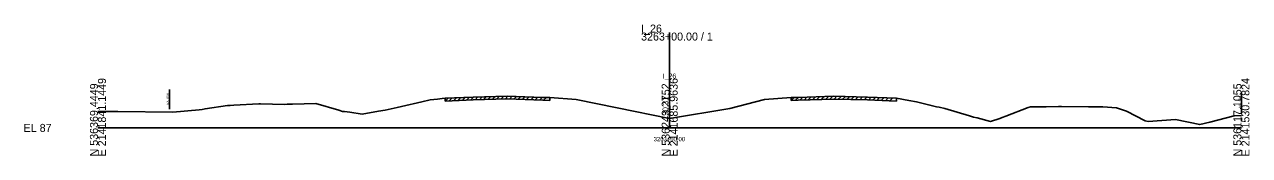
# Model space of a CAD drawing. Extents: x -13101 to 4803, y -924 to 22390.
# Drawn here: x 2974.3 to 3402.8, y 11490.3 to 11536.3 of the extents above; entities that cross this region are included whole.
import ezdxf

# ---------------------------------------------------------------- set-up
doc = ezdxf.new("R2010")
doc.units = 0
for name, color, linetype in [('RD_GPK_XS_Cell', 7, 'Continuous'), ('RD_XS_ExGround', 7, 'Continuous'), ('RD_XS_ExPaveRet', 7, 'Continuous'), ('RD_XS_ExRW', 7, 'Continuous'), ('RD_XS_TX_Baseline', 7, 'Continuous'), ('RD_XS_TX_Elev_EX', 7, 'Continuous'), ('RD_XS_TX_Station', 7, 'Continuous')]:
    doc.layers.add(name, color=color, linetype=linetype)

msp = doc.modelspace()

# ---------------------------------------------------------------- linework, layer by layer
at = {"layer": 'RD_GPK_XS_Cell'}
for p, q in [((3200, 11500), (3200, 11533.42)), ((3000, 11500), (3200, 11500)), ((3200, 11500), (3400, 11500))]:
    msp.add_line(p, q, dxfattribs=at)
at = {"layer": 'RD_XS_ExGround'}
msp.add_lwpolyline([(3000, 11505.78), (3006.19, 11505.77), (3006.99, 11505.77), (3026.2, 11505.49), (3035.4, 11506.29), (3036.49, 11506.46), (3037.47, 11506.71), (3045.37, 11507.86), (3046.21, 11507.88), (3047.56, 11507.96), (3056.3, 11508.42), (3056.84, 11508.45), (3065.24, 11508.24), (3066.22, 11508.32), (3068.08, 11508.36), (3076.22, 11508.59), (3084.29, 11506.27), (3085.52, 11505.73), (3086.23, 11505.72), (3088.07, 11505.49), (3092.44, 11504.87), (3098.2, 11505.9), (3100.45, 11506.25), (3104.65, 11507.19), (3106.23, 11507.56), (3113.29, 11509.19), (3116.24, 11509.88), (3118.82, 11510.11), (3120.43, 11510.26), (3121.42, 11510.37), (3131.22, 11510.83), (3143.14, 11511.14), (3155.6, 11510.7), (3158.11, 11510.64), (3167.24, 11510), (3181.62, 11507.05), (3200, 11503.31), (3221, 11506.84), (3233.12, 11509.99), (3242.5, 11510.61), (3244.9, 11510.71), (3257.44, 11511.1), (3269.2, 11510.79), (3279.31, 11510.38), (3283.66, 11509.63), (3286.31, 11509.09), (3291.06, 11508), (3293.35, 11507.43), (3294.25, 11507.23), (3296.31, 11506.76), (3304.92, 11504.27), (3306.31, 11503.82), (3307.57, 11503.54), (3312.22, 11502.3), (3315.52, 11503.3), (3316.32, 11503.61), (3317.64, 11504.07), (3325.36, 11507.18), (3326.24, 11507.34), (3331.72, 11507.37), (3336.03, 11507.48), (3337.09, 11507.5), (3346.48, 11507.41), (3351.56, 11507.4), (3356.35, 11507.06), (3359.84, 11505.83), (3366.38, 11502.47), (3367.44, 11502.29), (3376.92, 11502.93), (3385.41, 11501.18), (3388.97, 11501.99), (3397.49, 11504.2), (3400, 11504.3)], dxfattribs=at)
at = {"layer": 'RD_XS_ExPaveRet'}
for p, q in [((3121.42, 11509.37), (3122.47, 11510.42)), ((3122.92, 11509.44), (3123.97, 11510.49)), ((3124.42, 11509.51), (3125.47, 11510.56)), ((3125.92, 11509.58), (3126.97, 11510.63)), ((3127.42, 11509.65), (3128.47, 11510.7)), ((3128.92, 11509.72), (3129.97, 11510.77)), ((3130.42, 11509.79), (3131.46, 11510.84)), ((3131.92, 11509.85), (3132.95, 11510.87)), ((3133.42, 11509.89), (3134.45, 11510.91)), ((3134.92, 11509.93), (3135.95, 11510.95)), ((3136.42, 11509.97), (3137.45, 11510.99)), ((3137.92, 11510), (3138.95, 11511.03)), ((3139.42, 11510.04), (3140.45, 11511.07)), ((3140.92, 11510.08), (3141.95, 11511.11)), ((3142.42, 11510.12), (3143.43, 11511.13)), ((3143.92, 11510.11), (3144.89, 11511.08)), ((3145.42, 11510.06), (3146.39, 11511.03)), ((3146.92, 11510.01), (3147.89, 11510.97)), ((3148.42, 11509.96), (3149.39, 11510.92)), ((3149.92, 11509.9), (3150.89, 11510.87)), ((3151.42, 11509.85), (3152.39, 11510.82)), ((3152.92, 11509.8), (3153.89, 11510.76)), ((3154.42, 11509.74), (3155.39, 11510.71)), ((3155.92, 11509.69), (3156.9, 11510.67)), ((3158.11, 11510.64), (3158.11, 11509.64)), ((3242.5, 11509.61), (3243.54, 11510.65)), ((3242.5, 11509.61), (3242.5, 11510.61)), ((3244, 11509.67), (3245.04, 11510.71)), ((3245.5, 11509.73), (3246.53, 11510.76)), ((3247, 11509.77), (3248.03, 11510.81)), ((3248.5, 11509.82), (3249.53, 11510.85)), ((3250, 11509.87), (3251.03, 11510.9)), ((3251.5, 11509.91), (3252.53, 11510.95)), ((3253, 11509.96), (3254.03, 11510.99)), ((3254.5, 11510.01), (3255.53, 11511.04)), ((3256, 11510.06), (3257.03, 11511.09)), ((3257.5, 11510.1), (3258.47, 11511.07)), ((3259, 11510.06), (3259.97, 11511.03)), ((3260.5, 11510.02), (3261.47, 11511)), ((3262, 11509.98), (3262.97, 11510.96)), ((3263.5, 11509.94), (3264.47, 11510.92)), ((3265, 11509.9), (3265.97, 11510.88)), ((3266.5, 11509.86), (3267.47, 11510.84)), ((3268, 11509.82), (3268.97, 11510.8)), ((3269.5, 11509.78), (3270.46, 11510.74)), ((3271, 11509.72), (3271.96, 11510.68)), ((3272.5, 11509.66), (3273.46, 11510.62)), ((3274, 11509.6), (3274.96, 11510.56)), ((3275.5, 11509.53), (3276.46, 11510.49)), ((3277, 11509.47), (3277.96, 11510.43)), ((3121.42, 11509.37), (3121.42, 11510.37)), ((3121.42, 11509.37), (3131.22, 11509.83)), ((3131.22, 11509.83), (3143.14, 11510.14)), ((3143.14, 11510.14), (3155.6, 11509.7)), ((3155.6, 11509.7), (3158.11, 11509.64)), ((3242.5, 11509.61), (3244.9, 11509.71)), ((3244.9, 11509.71), (3257.44, 11510.1)), ((3257.44, 11510.1), (3269.2, 11509.79)), ((3269.2, 11509.79), (3279.31, 11509.38)), ((3279.31, 11510.38), (3279.31, 11509.38))]:
    msp.add_line(p, q, dxfattribs=at)
at = {"layer": 'RD_XS_ExRW'}
for p, q in [((3025, 11506.51), (3025, 11513.51)), ((3400, 11505.3), (3400, 11512.3))]:
    msp.add_line(p, q, dxfattribs=at)

# ---------------------------------------------------------------- texts
at = {"layer": 'RD_GPK_XS_Cell'}
for s, p in [('I_26', (3190, 11533.42)), ('3263+00.00 / 1', (3190, 11530.62)), ('EL 87', (2974, 11498.6))]:
    msp.add_text(s, height=2.8, dxfattribs=at).set_placement(p)
for s, p in [('N 536369.4449', (3000, 11490)), ('E 2141841.1449', (3002.8, 11490)), ('N 536243.2752', (3200, 11490)), ('E 2141685.9636', (3202.8, 11490)), ('N 536117.1055', (3400, 11490)), ('E 2141530.7824', (3402.8, 11490))]:
    msp.add_text(s, height=2.8, rotation=90, dxfattribs=at).set_placement(p)
at = {"layer": 'RD_XS_ExRW'}
for p in [(3024.75, 11508.19), (3399.75, 11506.98)]:
    msp.add_text('EX. R/W ', height=0.75, rotation=90, dxfattribs=at).set_placement(p)
at = {"layer": 'RD_XS_TX_Baseline'}
msp.add_text('I_26', height=1.75, dxfattribs=at).set_placement((3197.6, 11517.31))
at = {"layer": 'RD_XS_TX_Elev_EX'}
msp.add_text('90.31', height=2, rotation=90, dxfattribs=at).set_placement((3199.5, 11504.31))
at = {"layer": 'RD_XS_TX_Station'}
msp.add_text('3263+00.00', height=1.5, dxfattribs=at).set_placement((3194.4, 11495.31))

doc.saveas('drawing.dxf')
